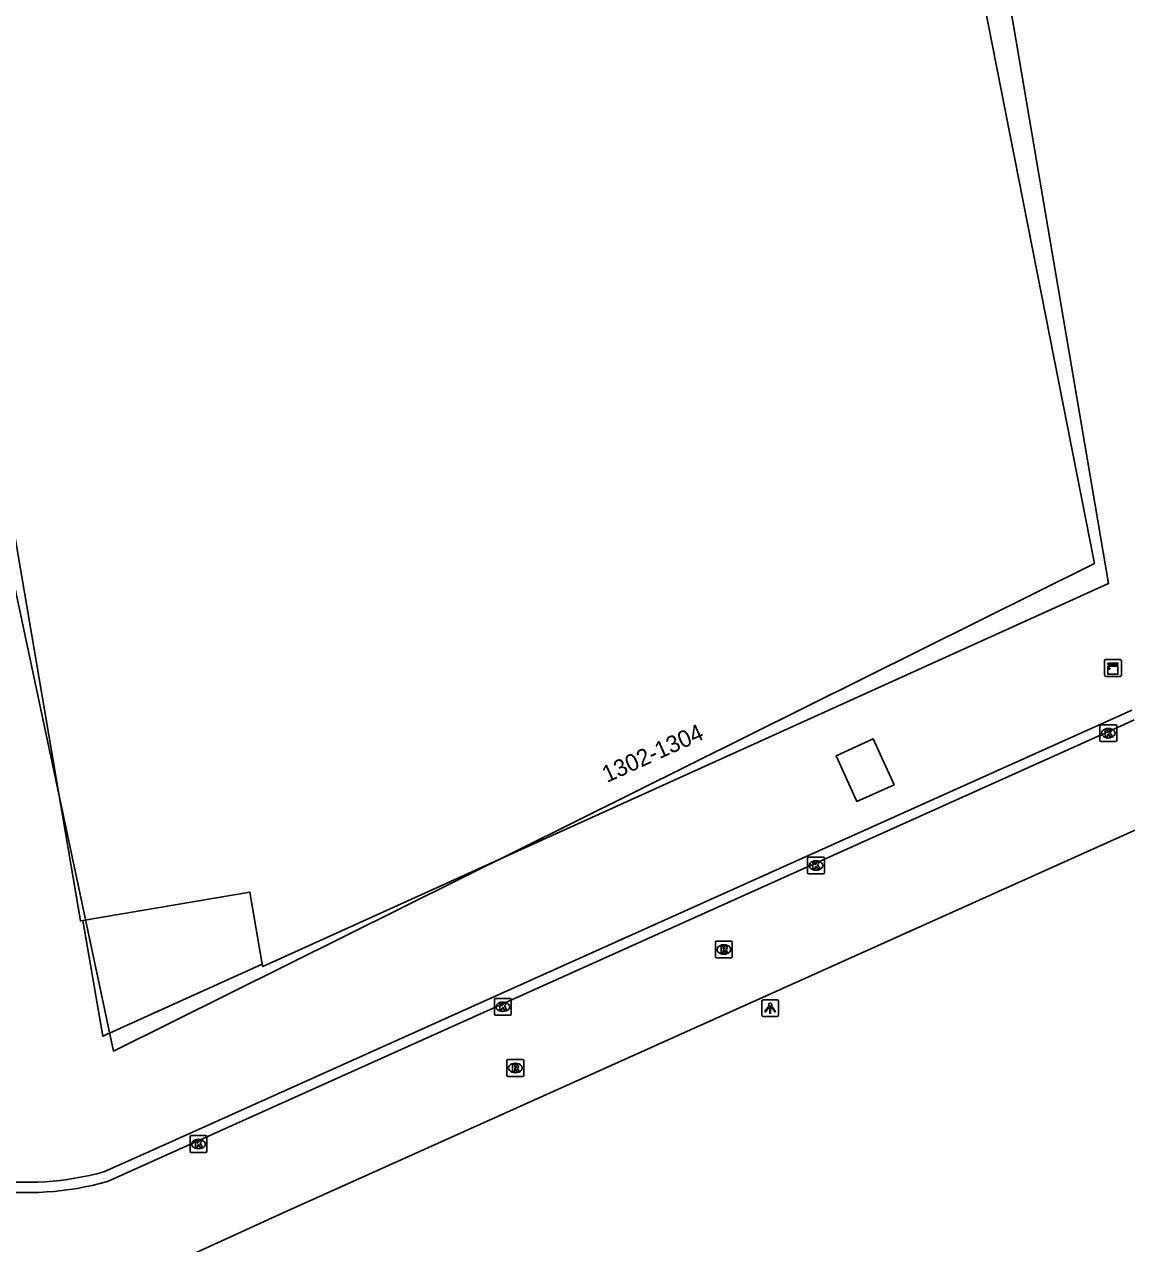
# Model space of a CAD drawing. Extents: x 154324 to 155743, y 382939 to 384183.
# Drawn here: x 154636.6 to 154702, y 383016.5 to 383088.8 of the extents above; entities that cross this region are included whole.
import ezdxf

# ---------------------------------------------------------------- set-up
doc = ezdxf.new("R2010")
doc.units = 0
for name, color, linetype in [('IMGEO_Erf', 7, 'Continuous'), ('IMGEO_Kast', 7, 'Continuous'), ('IMGEO_Kolk', 7, 'Continuous'), ('IMGEO_Lage_trafo', 7, 'Continuous'), ('IMGEO_Lichtpunt', 7, 'Continuous'), ('IMGEO_Pand', 7, 'Continuous'), ('IMGEO_Pand_nummerreeks', 7, 'Continuous'), ('IMGEO_Pand_vergunning_verleend', 7, 'Continuous'), ('IMGEO_Rijbaan_lokaal_gesloten', 7, 'Continuous'), ('IMGEO_Rioolput', 7, 'Continuous')]:
    doc.layers.add(name, color=color, linetype=linetype)

msp = doc.modelspace()

# ---------------------------------------------------------------- linework, layer by layer
at = {"layer": 'IMGEO_Erf'}
msp.add_lwpolyline([(154650.751, 383033.044), (154641.287, 383028.766), (154640.116, 383035.626)], dxfattribs=at)
at = {"layer": 'IMGEO_Kast'}
for p, q in [((154700.721, 383050.18), (154700.721, 383051.021)), ((154700.721, 383051.021), (154700.721, 383050.18)), ((154700.796, 383051.105), (154701.637, 383051.105)), ((154701.637, 383051.105), (154700.796, 383051.105)), ((154701.721, 383051.03), (154701.721, 383050.189)), ((154701.721, 383050.189), (154701.721, 383051.03)), ((154701.646, 383050.105), (154700.805, 383050.105)), ((154700.805, 383050.105), (154701.646, 383050.105))]:
    msp.add_line(p, q, dxfattribs=at)
for points in [[(154700.916, 383050.895), (154701.516, 383050.895), (154701.516, 383050.81), (154700.916, 383050.81), (154700.916, 383050.895)], [(154700.916, 383050.72), (154701.516, 383050.72), (154701.516, 383050.231), (154700.916, 383050.231), (154700.916, 383050.72)]]:
    msp.add_lwpolyline(points, dxfattribs=at)
msp.add_circle((154701, 383050.569), 0.0377, dxfattribs=at)
for centre, start, end in [((154700.799, 383051.027), 92.4484, 184.28452), ((154700.799, 383051.027), 92.4484, 184.28452), ((154701.643, 383051.027), 2.4484, 94.28452), ((154701.643, 383051.027), 2.4484, 94.28452), ((154700.799, 383050.183), 182.4484, 274.28452), ((154700.799, 383050.183), 182.4484, 274.28452), ((154701.643, 383050.183), 272.4484, 4.28452), ((154701.643, 383050.183), 272.4484, 4.28452)]:
    msp.add_arc(centre, 0.0779, start, end, dxfattribs=at)
at = {"layer": 'IMGEO_Kolk'}
for p, q in [((154700.442, 383046.309), (154700.442, 383047.161)), ((154700.517, 383047.235), (154701.369, 383047.235)), ((154700.93, 383047.015), (154700.955, 383047.015)), ((154701.443, 383047.161), (154701.443, 383046.309)), ((154701.369, 383046.235), (154700.517, 383046.235)), ((154700.953, 383046.455), (154700.928, 383046.455)), ((154683.099, 383038.464), (154683.099, 383039.316)), ((154683.174, 383039.39), (154684.026, 383039.39)), ((154683.587, 383039.17), (154683.612, 383039.17)), ((154684.1, 383039.316), (154684.1, 383038.464)), ((154684.026, 383038.39), (154683.174, 383038.39)), ((154683.61, 383038.61), (154683.585, 383038.61)), ((154664.525, 383030.086), (154664.525, 383030.938)), ((154664.6, 383031.012), (154665.452, 383031.012)), ((154665.013, 383030.792), (154665.038, 383030.792)), ((154665.526, 383030.938), (154665.526, 383030.086)), ((154665.452, 383030.012), (154664.6, 383030.012)), ((154665.036, 383030.232), (154665.011, 383030.232)), ((154646.471, 383021.945), (154646.471, 383022.797)), ((154646.546, 383022.871), (154647.398, 383022.871)), ((154647.472, 383022.797), (154647.472, 383021.945)), ((154646.982, 383022.091), (154646.957, 383022.091)), ((154646.959, 383022.651), (154646.984, 383022.651)), ((154647.398, 383021.871), (154646.546, 383021.871))]:
    msp.add_line(p, q, dxfattribs=at)
for points in [[(154700.442, 383046.309), (154700.442, 383047.161)], [(154700.517, 383047.235), (154701.369, 383047.235)], [(154700.763, 383046.935), (154700.886, 383046.935), (154700.886, 383046.784), (154701.016, 383046.935), (154701.18, 383046.935), (154701.034, 383046.784), (154701.187, 383046.535), (154701.035, 383046.535), (154700.95, 383046.699), (154700.886, 383046.632), (154700.886, 383046.535), (154700.763, 383046.535), (154700.763, 383046.935)], [(154701.443, 383047.161), (154701.443, 383046.309)], [(154701.369, 383046.235), (154700.517, 383046.235)], [(154683.099, 383038.464), (154683.099, 383039.316)], [(154683.174, 383039.39), (154684.026, 383039.39)], [(154683.42, 383039.09), (154683.543, 383039.09), (154683.543, 383038.939), (154683.673, 383039.09), (154683.837, 383039.09), (154683.691, 383038.939), (154683.844, 383038.69), (154683.692, 383038.69), (154683.607, 383038.854), (154683.543, 383038.787), (154683.543, 383038.69), (154683.42, 383038.69), (154683.42, 383039.09)], [(154684.1, 383039.316), (154684.1, 383038.464)], [(154684.026, 383038.39), (154683.174, 383038.39)], [(154664.525, 383030.086), (154664.525, 383030.938)], [(154664.6, 383031.012), (154665.452, 383031.012)], [(154665.526, 383030.938), (154665.526, 383030.086)], [(154665.452, 383030.012), (154664.6, 383030.012)], [(154664.846, 383030.712), (154664.969, 383030.712), (154664.969, 383030.561), (154665.099, 383030.712), (154665.263, 383030.712), (154665.117, 383030.561), (154665.27, 383030.312), (154665.118, 383030.312), (154665.033, 383030.476), (154664.969, 383030.409), (154664.969, 383030.312), (154664.846, 383030.312), (154664.846, 383030.712)], [(154646.471, 383021.945), (154646.471, 383022.797)], [(154646.546, 383022.871), (154647.398, 383022.871)], [(154647.472, 383022.797), (154647.472, 383021.945)], [(154646.792, 383022.571), (154646.915, 383022.571), (154646.915, 383022.42), (154647.045, 383022.571), (154647.209, 383022.571), (154647.063, 383022.42), (154647.216, 383022.171), (154647.064, 383022.171), (154646.979, 383022.335), (154646.915, 383022.268), (154646.915, 383022.171), (154646.792, 383022.171), (154646.792, 383022.571)], [(154647.398, 383021.871), (154646.546, 383021.871)]]:
    msp.add_lwpolyline(points, dxfattribs=at)
for centre, start, end in [((154700.519, 383047.159), 91.55205, 178.44795), ((154700.519, 383047.159), 91.55205, 178.44795), ((154701.367, 383047.159), 1.55205, 88.44795), ((154701.367, 383047.159), 1.55205, 88.44795), ((154700.519, 383046.311), 181.55205, 268.44795), ((154700.519, 383046.311), 181.55205, 268.44795), ((154701.367, 383046.311), 271.55205, 358.44795), ((154701.367, 383046.311), 271.55205, 358.44795), ((154683.176, 383039.314), 91.55205, 178.44795), ((154683.176, 383039.314), 91.55205, 178.44795), ((154684.024, 383039.314), 1.55205, 88.44795), ((154684.024, 383039.314), 1.55205, 88.44795), ((154683.176, 383038.466), 181.55205, 268.44795), ((154683.176, 383038.466), 181.55205, 268.44795), ((154684.024, 383038.466), 271.55205, 358.44795), ((154684.024, 383038.466), 271.55205, 358.44795), ((154664.602, 383030.936), 91.55205, 178.44795), ((154664.602, 383030.936), 91.55205, 178.44795), ((154665.45, 383030.936), 1.55205, 88.44795), ((154665.45, 383030.936), 1.55205, 88.44795), ((154664.602, 383030.088), 181.55205, 268.44795), ((154664.602, 383030.088), 181.55205, 268.44795), ((154665.45, 383030.088), 271.55205, 358.44795), ((154665.45, 383030.088), 271.55205, 358.44795), ((154646.548, 383022.795), 91.55205, 178.44795), ((154646.548, 383022.795), 91.55205, 178.44795), ((154647.396, 383022.795), 1.55205, 88.44795), ((154647.396, 383022.795), 1.55205, 88.44795), ((154646.548, 383021.947), 181.55205, 268.44795), ((154646.548, 383021.947), 181.55205, 268.44795), ((154647.396, 383021.947), 271.55205, 358.44795), ((154647.396, 383021.947), 271.55205, 358.44795)]:
    msp.add_arc(centre, 0.0765, start, end, dxfattribs=at)
for centre, major_axis, ratio, start_param, end_param in [((154700.929, 383046.735), (-0.387, 0.002), 0.722429, 4.712389, 7.853982), ((154700.954, 383046.735), (-0.39, 0.002), 0.717154, 1.570796, 4.712389), ((154683.586, 383038.89), (-0.387, 0.002), 0.722429, 4.712389, 7.853982), ((154683.611, 383038.89), (-0.39, 0.002), 0.717154, 1.570796, 4.712389), ((154665.012, 383030.512), (-0.387, 0.002), 0.722429, 4.712389, 7.853982), ((154665.037, 383030.512), (-0.39, 0.002), 0.717154, 1.570796, 4.712389), ((154646.958, 383022.371), (-0.387, 0.002), 0.722429, 4.712389, 7.853982), ((154646.983, 383022.371), (-0.39, 0.002), 0.717154, 1.570796, 4.712389)]:
    msp.add_ellipse(centre, major_axis=major_axis, ratio=ratio, start_param=start_param, end_param=end_param, dxfattribs=at)
at = {"layer": 'IMGEO_Lage_trafo'}
msp.add_lwpolyline([(154688.229, 383043.667), (154686.033, 383042.676), (154684.802, 383045.401), (154686.999, 383046.392), (154688.229, 383043.667)], dxfattribs=at)
at = {"layer": 'IMGEO_Lichtpunt'}
for p, q in [((154680.386, 383030.836), (154680.386, 383030.029)), ((154680.386, 383030.836), (154680.386, 383030.029)), ((154681.288, 383030.931), (154680.48, 383030.931)), ((154681.288, 383030.931), (154680.48, 383030.931)), ((154681.382, 383030.029), (154681.382, 383030.836)), ((154681.382, 383030.029), (154681.382, 383030.836)), ((154680.48, 383029.935), (154681.288, 383029.935)), ((154680.48, 383029.935), (154681.288, 383029.935))]:
    msp.add_line(p, q, dxfattribs=at)
for points in [[(154680.76, 383030.5), (154680.799, 383030.472), (154680.611, 383030.21), (154680.573, 383030.237), (154680.76, 383030.5)], [(154680.862, 383030.452), (154680.909, 383030.452), (154680.909, 383030.13), (154680.862, 383030.13), (154680.862, 383030.452)], [(154680.972, 383030.472), (154681.01, 383030.499), (154681.197, 383030.237), (154681.158, 383030.209), (154680.972, 383030.472)]]:
    msp.add_lwpolyline(points, dxfattribs=at)
msp.add_circle((154680.885, 383030.634), 0.0994, dxfattribs=at)
for centre, start, end in [((154680.48, 383030.836), 90, 180), ((154680.48, 383030.836), 90, 180), ((154681.288, 383030.836), 0, 90), ((154681.288, 383030.836), 0, 90), ((154680.48, 383030.029), 180, 270), ((154680.48, 383030.029), 180, 270), ((154681.288, 383030.029), 270, 0), ((154681.288, 383030.029), 270, 360)]:
    msp.add_arc(centre, 0.0946, start, end, dxfattribs=at)
at = {"layer": 'IMGEO_Pand'}
for points in [[(154640.116, 383035.626), (154639.963, 383035.6), (154623.689, 383130.917), (154616.871, 383129.755), (154616.832, 383129.748), (154616.708, 383130.477), (154612.736, 383129.8), (154612.106, 383133.492), (154611.258, 383133.348), (154609.37, 383144.423), (154609.222, 383144.398), (154590.396, 383254.849), (154588.656, 383265.073), (154600.502, 383267.079)], [(154678.388, 383188.109), (154700.956, 383055.605), (154650.777, 383032.891), (154650.751, 383033.044)], [(154640.116, 383035.626), (154650.021, 383037.317), (154650.751, 383033.044)]]:
    msp.add_lwpolyline(points, dxfattribs=at)
at = {"layer": 'IMGEO_Pand_vergunning_verleend'}
msp.add_lwpolyline([(154584.715, 383256.808), (154657.955, 383270.711), (154700.131, 383056.801), (154641.926, 383027.883), (154620.799, 383127.072), (154608.343, 383124.842), (154584.715, 383256.808)], dxfattribs=at)
at = {"layer": 'IMGEO_Rijbaan_lokaal_gesloten'}
for points in [[(154641.36, 383020.718), (154644.058, 383021.92), (154701.677, 383047.796), (154702.336, 383048.109)], [(154641.566, 383020.143), (154644.31, 383021.367), (154701.889, 383047.258), (154702.471, 383047.534)], [(154703.005, 383041.199), (154652.034, 383018.306), (154642.78, 383014.081)]]:
    msp.add_lwpolyline(points, dxfattribs=at)
for centre, radius, start, end in [((154636.759, 383037.485), 17.996, 238.9474, 285.49324), ((154636.745, 383037.707), 17.605, 239.47001, 285.19734)]:
    msp.add_arc(centre, radius, start, end, dxfattribs=at)
at = {"layer": 'IMGEO_Rioolput'}
for p, q in [((154677.635, 383033.484), (154677.635, 383034.336)), ((154677.71, 383034.41), (154678.562, 383034.41)), ((154678.636, 383034.336), (154678.636, 383033.484)), ((154678.146, 383033.63), (154678.121, 383033.63)), ((154678.123, 383034.19), (154678.148, 383034.19)), ((154678.562, 383033.41), (154677.71, 383033.41)), ((154665.266, 383026.456), (154665.266, 383027.308)), ((154665.341, 383027.382), (154666.193, 383027.382)), ((154665.754, 383027.162), (154665.779, 383027.162)), ((154666.267, 383027.308), (154666.267, 383026.456)), ((154665.777, 383026.602), (154665.752, 383026.602)), ((154666.193, 383026.382), (154665.341, 383026.382))]:
    msp.add_line(p, q, dxfattribs=at)
for points in [[(154677.635, 383033.484), (154677.635, 383034.336)], [(154677.71, 383034.41), (154678.562, 383034.41)], [(154678.636, 383034.336), (154678.636, 383033.484)], [(154678.224, 383034.108), (154677.972, 383034.11), (154677.972, 383033.71)], [(154677.972, 383033.71), (154678.096, 383033.71), (154678.096, 383033.872), (154678.107, 383033.872)], [(154678.15, 383034.029), (154678.096, 383034.029), (154678.096, 383033.948)], [(154678.096, 383033.948), (154678.148, 383033.948)], [(154678.154, 383033.843), (154678.225, 383033.71), (154678.365, 383033.71), (154678.3, 383033.836)], [(154678.562, 383033.41), (154677.71, 383033.41)], [(154665.266, 383026.456), (154665.266, 383027.308)], [(154665.341, 383027.382), (154666.193, 383027.382)], [(154666.267, 383027.308), (154666.267, 383026.456)], [(154665.855, 383027.08), (154665.603, 383027.082), (154665.603, 383026.682)], [(154665.603, 383026.682), (154665.727, 383026.682), (154665.727, 383026.844), (154665.738, 383026.844)], [(154665.781, 383027.001), (154665.727, 383027.001), (154665.727, 383026.92)], [(154665.727, 383026.92), (154665.779, 383026.92)], [(154665.785, 383026.815), (154665.856, 383026.682), (154665.996, 383026.682), (154665.931, 383026.808)], [(154666.193, 383026.382), (154665.341, 383026.382)]]:
    msp.add_lwpolyline(points, dxfattribs=at)
for centre, radius, start, end in [((154677.712, 383034.334), 0.0765, 91.55205, 178.44795), ((154677.712, 383034.334), 0.0765, 91.55205, 178.44795), ((154678.56, 383034.334), 0.0765, 1.55205, 88.44795), ((154678.56, 383034.334), 0.0765, 1.55205, 88.44795), ((154678.106, 383033.819), 0.0533, 26.02933, 88.69889), ((154678.132, 383034.137), 0.19, 274.7715, 282.96867), ((154678.156, 383033.933), 0.0964, 77.00612, 93.18647), ((154678.17, 383033.99), 0.0378, 276.66336, 79.67722), ((154678.223, 383033.998), 0.109, 350.36119, 89.41601), ((154678.221, 383033.998), 0.112, 277.58423, 350.98172), ((154678.205, 383033.783), 0.108, 29.51342, 73.79051), ((154677.712, 383033.486), 0.0765, 181.55205, 268.44795), ((154677.712, 383033.486), 0.0765, 181.55205, 268.44795), ((154678.56, 383033.486), 0.0765, 271.55205, 358.44795), ((154678.56, 383033.486), 0.0765, 271.55205, 358.44795), ((154665.343, 383027.306), 0.0765, 91.55205, 178.44795), ((154665.343, 383027.306), 0.0765, 91.55205, 178.44795), ((154666.191, 383027.306), 0.0765, 1.55205, 88.44795), ((154666.191, 383027.306), 0.0765, 1.55205, 88.44795), ((154665.343, 383026.458), 0.0765, 181.55205, 268.44795), ((154665.343, 383026.458), 0.0765, 181.55205, 268.44795), ((154665.737, 383026.791), 0.0533, 26.02933, 88.69889), ((154665.763, 383027.109), 0.19, 274.7715, 282.96867), ((154665.787, 383026.905), 0.0964, 77.00612, 93.18647), ((154665.801, 383026.962), 0.0378, 276.66336, 79.67722), ((154665.854, 383026.97), 0.109, 350.36119, 89.41601), ((154665.852, 383026.97), 0.112, 277.58423, 350.98172), ((154665.836, 383026.755), 0.108, 29.51342, 73.79051), ((154666.191, 383026.458), 0.0765, 271.55205, 358.44795), ((154666.191, 383026.458), 0.0765, 271.55205, 358.44795)]:
    msp.add_arc(centre, radius, start, end, dxfattribs=at)
for centre, major_axis, ratio, start_param, end_param in [((154678.122, 383033.91), (-0.387, 0.002), 0.722429, 4.712389, 7.853982), ((154678.147, 383033.91), (-0.39, 0.002), 0.717154, 1.570796, 4.712389), ((154665.753, 383026.882), (-0.387, 0.002), 0.722429, 4.712389, 7.853982), ((154665.778, 383026.882), (-0.39, 0.002), 0.717154, 1.570796, 4.712389)]:
    msp.add_ellipse(centre, major_axis=major_axis, ratio=ratio, start_param=start_param, end_param=end_param, dxfattribs=at)

# ---------------------------------------------------------------- texts
at = {"layer": 'IMGEO_Pand_nummerreeks'}
msp.add_text('1302-1304', height=1, rotation=24.35644, dxfattribs=at).set_placement((154671.197, 383043.78))

doc.saveas('drawing.dxf')
